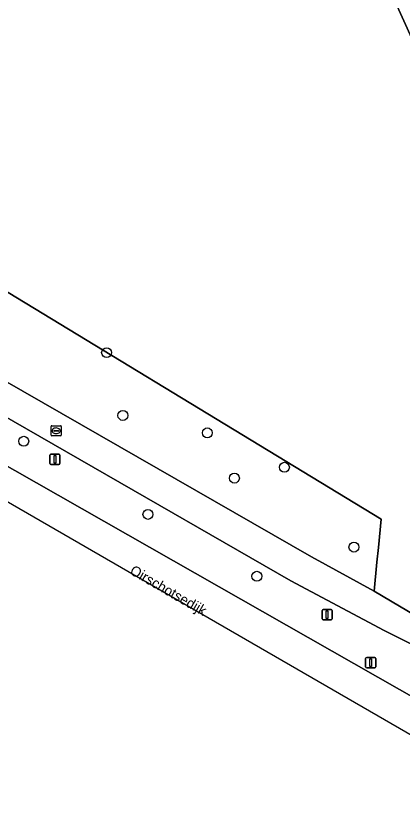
# Model space of a CAD drawing. Extents: x 157132 to 159279, y 384991 to 386650.
# Drawn here: x 159009.3 to 159047.3, y 384999.6 to 385077.6 of the extents above; entities that cross this region are included whole.
import ezdxf

# ---------------------------------------------------------------- set-up
doc = ezdxf.new("R2010")
doc.units = 0
for name, color, linetype in [('IMGEO_Boom', 7, 'Continuous'), ('IMGEO_Gemengd_bos', 7, 'Continuous'), ('IMGEO_Groenvoorziening', 7, 'Continuous'), ('IMGEO_Lichtmast', 7, 'Continuous'), ('IMGEO_Openbare_ruimte_label', 7, 'Continuous'), ('IMGEO_Rijbaan_lokaal_gesloten', 7, 'Continuous'), ('IMGEO_Rioolput', 7, 'Continuous'), ('IMGEO_Verkeersbordpaal', 7, 'Continuous'), ('IMGEO_Voetpad_open', 7, 'Continuous')]:
    doc.layers.add(name, color=color, linetype=linetype)

msp = doc.modelspace()

# ---------------------------------------------------------------- linework, layer by layer
at = {"layer": 'IMGEO_Boom'}
for centre in [(159018.252, 385044.398), (159019.855, 385038.21), (159028.166, 385036.499), (159010.098, 385035.672), (159035.748, 385033.109), (159030.828, 385032.043), (159022.319, 385028.47), (159042.59, 385025.245), (159033.037, 385022.378)]:
    msp.add_circle(centre, 0.489, dxfattribs=at)
at = {"layer": 'IMGEO_Gemengd_bos'}
msp.add_lwpolyline([(158994.894, 385049.258), (159038.423, 385024.282), (159044.566, 385020.904), (159044.854, 385023.771), (159044.999, 385025.216), (159045.279, 385028.002), (159000, 385055.503)], dxfattribs=at)
at = {"layer": 'IMGEO_Groenvoorziening'}
for points in [[(159014.909, 385156.576), (159013.145, 385153.422), (159027.263, 385121.739), (159068.515, 385030.696), (159071.143, 385032.868), (159071.37, 385033.085), (159044.824, 385091.61), (159015.899, 385155.76)], [(159071.37, 385033.085), (159071.143, 385032.868), (159068.515, 385030.696), (159027.263, 385121.739)], [(158951.346, 385065.855), (158991.219, 385043.034), (159051.559, 385008.655), (159053.436, 385007.595), (159062.513, 385002.544), (159064.692, 385005.722), (159049.104, 385015.263), (159045.577, 385017.044), (159036.37, 385021.937), (158953.292, 385069.711)], [(159000, 385055.503), (159045.279, 385028.002), (159044.999, 385025.216), (159044.854, 385023.771), (159044.566, 385020.904), (159066.288, 385008.051), (159067.434, 385009.722), (159068.646, 385008.884), (159070.784, 385013.725)]]:
    msp.add_lwpolyline(points, dxfattribs=at)
at = {"layer": 'IMGEO_Lichtmast'}
for p, q in [((159012.673, 385033.491), (159012.673, 385034.291)), ((159012.673, 385034.291), (159012.673, 385033.491)), ((159012.773, 385034.391), (159013.563, 385034.391)), ((159013.563, 385034.391), (159012.773, 385034.391)), ((159013.663, 385034.291), (159013.663, 385033.491)), ((159013.663, 385033.491), (159013.663, 385034.291)), ((159013.563, 385033.391), (159012.773, 385033.391)), ((159012.773, 385033.391), (159013.563, 385033.391)), ((159039.453, 385018.199), (159039.453, 385018.999)), ((159039.453, 385018.999), (159039.453, 385018.199)), ((159039.553, 385019.099), (159040.343, 385019.099)), ((159040.343, 385019.099), (159039.553, 385019.099)), ((159040.443, 385018.999), (159040.443, 385018.199)), ((159040.443, 385018.199), (159040.443, 385018.999)), ((159040.343, 385018.099), (159039.553, 385018.099)), ((159039.553, 385018.099), (159040.343, 385018.099))]:
    msp.add_line(p, q, dxfattribs=at)
for points in [[(159013.093, 385034.266), (159013.243, 385034.266), (159013.243, 385033.516), (159013.093, 385033.516), (159013.093, 385034.266)], [(159039.873, 385018.974), (159040.023, 385018.974), (159040.023, 385018.224), (159039.873, 385018.224), (159039.873, 385018.974)]]:
    msp.add_lwpolyline(points, dxfattribs=at)
for centre, start, end in [((159012.773, 385034.291), 90, 180), ((159012.773, 385034.291), 90, 180), ((159013.563, 385034.291), 0, 90), ((159013.563, 385034.291), 360, 90), ((159012.773, 385033.491), 180, 270), ((159012.773, 385033.491), 180, 270), ((159013.563, 385033.491), 270, 0), ((159013.563, 385033.491), 270, 0), ((159039.553, 385018.999), 90, 180), ((159039.553, 385018.999), 90, 180), ((159040.343, 385018.999), 0, 90), ((159040.343, 385018.999), 360, 90), ((159039.553, 385018.199), 180, 270), ((159039.553, 385018.199), 180, 270), ((159040.343, 385018.199), 270, 0), ((159040.343, 385018.199), 270, 0)]:
    msp.add_arc(centre, 0.1, start, end, dxfattribs=at)
at = {"layer": 'IMGEO_Rijbaan_lokaal_gesloten'}
for points in [[(157962.149, 385631.647), (157960.386, 385628.605), (158092.746, 385552.638), (158517.188, 385311.578), (158723.574, 385194.362), (159060.524, 384999.643)], [(159060.524, 384999.643), (159062.513, 385002.544), (159053.436, 385007.595), (159051.559, 385008.655), (158991.219, 385043.034), (158951.346, 385065.855), (158946.101, 385068.848), (158761.984, 385173.955), (158524.266, 385309.959)]]:
    msp.add_lwpolyline(points, dxfattribs=at)
at = {"layer": 'IMGEO_Rioolput'}
for p, q in [((159012.787, 385036.276), (159012.787, 385037.128)), ((159012.862, 385037.202), (159013.714, 385037.202)), ((159013.275, 385036.982), (159013.3, 385036.982)), ((159013.788, 385037.128), (159013.788, 385036.276)), ((159013.714, 385036.202), (159012.862, 385036.202)), ((159013.046, 385036.696), (159013.046, 385036.708)), ((159013.484, 385036.659), (159013.086, 385036.659)), ((159013.089, 385036.745), (159013.487, 385036.745)), ((159013.298, 385036.422), (159013.273, 385036.422)), ((159013.53, 385036.708), (159013.53, 385036.696))]:
    msp.add_line(p, q, dxfattribs=at)
for points in [[(159012.787, 385036.276), (159012.787, 385037.128)], [(159012.862, 385037.202), (159013.714, 385037.202)], [(159013.788, 385037.128), (159013.788, 385036.276)], [(159013.714, 385036.202), (159012.862, 385036.202)]]:
    msp.add_lwpolyline(points, dxfattribs=at)
for centre, radius, start, end in [((159012.864, 385037.126), 0.0765, 91.55205, 178.44795), ((159012.864, 385037.126), 0.0765, 91.55205, 178.44795), ((159013.712, 385037.126), 0.0765, 1.55205, 88.44795), ((159013.712, 385037.126), 0.0765, 1.55205, 88.44795), ((159012.864, 385036.278), 0.0765, 181.55205, 268.44795), ((159012.864, 385036.278), 0.0765, 181.55205, 268.44795), ((159013.086, 385036.705), 0.0403, 85.87752, 175.75265), ((159013.083, 385036.695), 0.0366, 178.93798, 274.71019), ((159013.487, 385036.702), 0.043, 264.86636, 352.45326), ((159013.491, 385036.707), 0.0386, 1.73085, 96.63898), ((159013.712, 385036.278), 0.0765, 271.55205, 358.44795), ((159013.712, 385036.278), 0.0765, 271.55205, 358.44795)]:
    msp.add_arc(centre, radius, start, end, dxfattribs=at)
for centre, major_axis, ratio, start_param, end_param in [((159013.274, 385036.702), (-0.387, 0.002), 0.722429, 4.712389, 7.853982), ((159013.299, 385036.702), (-0.39, 0.002), 0.717154, 1.570796, 4.712389)]:
    msp.add_ellipse(centre, major_axis=major_axis, ratio=ratio, start_param=start_param, end_param=end_param, dxfattribs=at)
at = {"layer": 'IMGEO_Verkeersbordpaal'}
for p, q in [((159043.843, 385014.37), (159044.633, 385014.37)), ((159044.633, 385014.37), (159043.843, 385014.37)), ((159043.743, 385013.47), (159043.743, 385014.27)), ((159043.743, 385014.27), (159043.743, 385013.47)), ((159044.733, 385014.27), (159044.733, 385013.47)), ((159044.733, 385013.47), (159044.733, 385014.27)), ((159044.633, 385013.37), (159043.843, 385013.37)), ((159043.843, 385013.37), (159044.633, 385013.37))]:
    msp.add_line(p, q, dxfattribs=at)
msp.add_lwpolyline([(159044.163, 385014.245), (159044.313, 385014.245), (159044.313, 385013.495), (159044.163, 385013.495), (159044.163, 385014.245)], dxfattribs=at)
for centre, start, end in [((159043.843, 385014.27), 90, 180), ((159043.843, 385014.27), 90, 180), ((159044.633, 385014.27), 0, 90), ((159044.633, 385014.27), 360, 90), ((159043.843, 385013.47), 180, 270), ((159043.843, 385013.47), 180, 270), ((159044.633, 385013.47), 270, 0), ((159044.633, 385013.47), 270, 0)]:
    msp.add_arc(centre, 0.1, start, end, dxfattribs=at)
at = {"layer": 'IMGEO_Voetpad_open'}
msp.add_lwpolyline([(158655.301, 385239.709), (158763.695, 385178.056), (158858.398, 385123.598), (158948.968, 385072.159), (158953.292, 385069.711), (159036.37, 385021.937), (159045.577, 385017.044), (159049.104, 385015.263), (159064.692, 385005.722), (159066.288, 385008.051), (159044.566, 385020.904), (159038.423, 385024.282), (158994.894, 385049.258), (158960.501, 385069.295), (158956.094, 385071.837), (158949.906, 385075.132), (158946, 385077.106), (158944.593, 385077.909), (158859.992, 385126.144), (158809.594, 385155.269), (158797.346, 385162.347), (158769.925, 385178.194), (158698.775, 385218.635)], dxfattribs=at)

# ---------------------------------------------------------------- texts
at = {"layer": 'IMGEO_Openbare_ruimte_label'}
msp.add_text('Oirschotsedijk', height=1, rotation=329.99927, dxfattribs=at).set_placement((159020.449, 385022.66))

doc.saveas('drawing.dxf')
